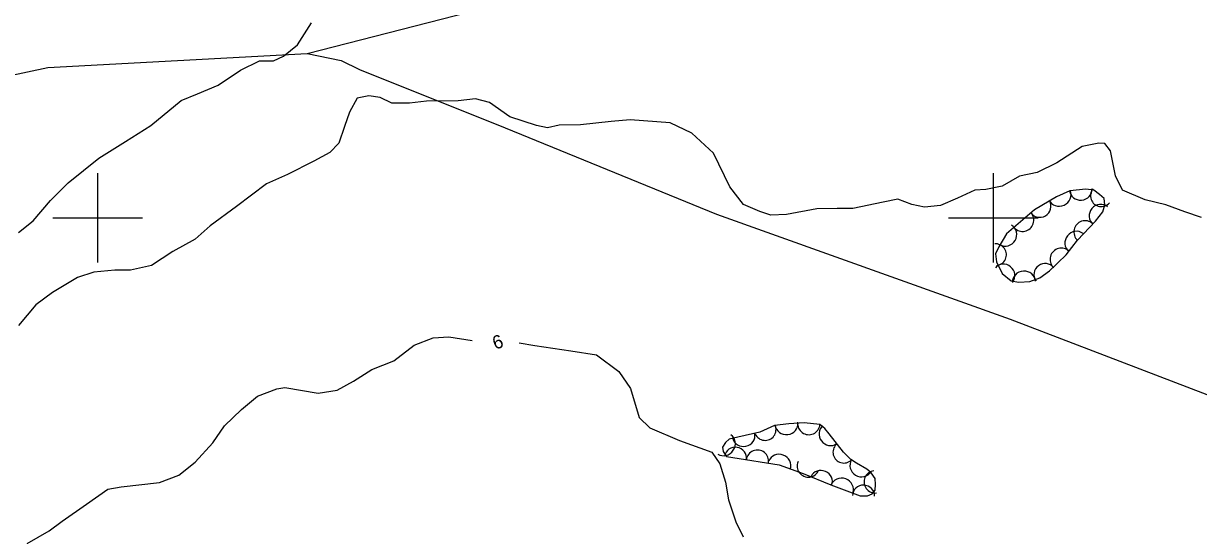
# Model space of a CAD drawing. Extents: x 643342 to 646936, y 5873857 to 5876103.
# Drawn here: x 645183.5 to 645445.8, y 5875329 to 5875443.4 of the extents above; entities that cross this region are included whole.
import ezdxf

# ---------------------------------------------------------------- set-up
doc = ezdxf.new("R2010")
doc.units = 0
for name, color, linetype in [('Niveau 1', 7, 'Continuous'), ('Niveau 2', 7, 'Continuous'), ('Niveau 22', 7, 'Continuous'), ('Niveau 44', 7, 'Continuous'), ('Niveau 61', 7, 'Continuous')]:
    doc.layers.add(name, color=color, linetype=linetype)

msp = doc.modelspace()

# ---------------------------------------------------------------- linework, layer by layer
at = {"layer": 'Niveau 1'}
msp.add_lwpolyline([(645182.37, 5875396.76), (645185.58, 5875399.33), (645189.49, 5875403.9), (645193.39, 5875407.82), (645196.82, 5875410.59), (645200.31, 5875413.3), (645206.2, 5875417.05), (645211.89, 5875420.6), (645218.67, 5875426.18), (645222.31, 5875427.74), (645226.91, 5875429.67), (645231.92, 5875432.99), (645236.15, 5875435.06), (645239.24, 5875435.05), (645241.47, 5875436.13), (645244.62, 5875438.63), (645247.79, 5875443.53)], dxfattribs=at)
at = {"layer": 'Niveau 2'}
for points in [[(645246.8, 5875436.74), (645309.81, 5875452.91), (645347.57, 5875463.16), (645370.52, 5875468.47), (645498.8, 5875495.97), (645554.04, 5875506.6), (645620.96, 5875521.54), (645671.93, 5875531.75), (645722.29, 5875544.6), (645729.55, 5875514.86), (645737.24, 5875468.76), (645738.05, 5875463.13)], [(645263.09, 5875426.89), (645260.56, 5875427.25), (645257.98, 5875426.72), (645256.22, 5875423.58), (645255.16, 5875420.44), (645253.87, 5875416.69), (645251.83, 5875414.63), (645248.28, 5875412.67), (645242.37, 5875409.68), (645237.72, 5875407.62), (645231, 5875402.51), (645225.14, 5875398.23), (645221.8, 5875395.23), (645216.79, 5875392.49), (645212.05, 5875389.37), (645207.31, 5875388.29), (645203.87, 5875388.28), (645199.12, 5875387.85), (645195.54, 5875386.7), (645189.95, 5875383.33), (645186.17, 5875380.58), (645182.37, 5875375.96)], [(645398.3, 5875406.32), (645395.88, 5875406.16), (645391.98, 5875404.41), (645388.23, 5875402.78), (645384.61, 5875402.39), (645381.83, 5875403.02), (645378.65, 5875404.14), (645375.4, 5875403.49), (645368.62, 5875402.06), (645365.14, 5875402.1), (645360.61, 5875402.04), (645353.81, 5875400.78), (645350.29, 5875400.58), (645347.89, 5875401.41), (645344.21, 5875402.95), (645341.18, 5875406.95), (645337.49, 5875414.45), (645332.67, 5875418.93), (645327.82, 5875421.19), (645318.93, 5875421.91), (645314.66, 5875421.52), (645307.8, 5875420.79), (645303.04, 5875420.71), (645300.42, 5875420.12), (645297.98, 5875420.66), (645292.06, 5875422.53), (645287.52, 5875425.75), (645284.37, 5875426.58), (645280.51, 5875426.11), (645273.47, 5875426.07), (645269.67, 5875425.61), (645265.71, 5875425.6), (645263.09, 5875426.89)], [(645446.51, 5875400.11), (645442.75, 5875401.34), (645438.49, 5875402.94), (645433.88, 5875403.99), (645428.87, 5875406.22), (645427.25, 5875409.41), (645426.18, 5875414.98), (645424.87, 5875416.61), (645423.59, 5875416.67), (645419.83, 5875415.92), (645414.19, 5875412.26), (645409.79, 5875410.16), (645405.87, 5875409.28), (645401.95, 5875407.06), (645398.3, 5875406.32)], [(645184.27, 5875327.23), (645189.17, 5875330.09), (645192.07, 5875332.23), (645197.52, 5875336.08), (645202.25, 5875339.39), (645205.24, 5875339.95), (645213.81, 5875340.91), (645218.16, 5875342.54), (645221.76, 5875345.39), (645225.7, 5875349.74), (645228.34, 5875353.56), (645232.1, 5875357.19), (645235.7, 5875360.16), (645240.05, 5875361.79), (645241.77, 5875362.12), (645249.23, 5875360.86), (645253.49, 5875361.54), (645257.11, 5875363.51), (645261.2, 5875366.11), (645266.15, 5875368.09), (645270.69, 5875371.55), (645274.92, 5875373.17), (645278.39, 5875373.42), (645283.66, 5875372.59)], [(645294.13, 5875372.12), (645297.63, 5875371.47), (645305.66, 5875370.27), (645311.39, 5875369.38), (645316.38, 5875365.67), (645318.99, 5875361.86), (645320.91, 5875355.41), (645323.32, 5875353.11), (645329.92, 5875350.26), (645337.15, 5875347.63), (645338.95, 5875345.04), (645340.19, 5875340.94), (645340.88, 5875337.01), (645342.54, 5875332.12), (645344.12, 5875328.75)]]:
    msp.add_lwpolyline(points, dxfattribs=at)
at = {"layer": 'Niveau 22'}
msp.add_lwpolyline([(644607.99, 5875276.54), (644615.34, 5875282.58), (644626.17, 5875289.28), (644635.97, 5875293.95), (644659.53, 5875302.81), (644722.84, 5875328.77), (644742.2, 5875336.13), (644757.56, 5875339.67), (644787.87, 5875347.1), (644846.76, 5875359.49), (644883.37, 5875366.24), (644949.1, 5875380.73), (645027.75, 5875398.1), (645075.65, 5875409.44), (645188.89, 5875433.56), (645246.8, 5875436.74), (645254.39, 5875435.12), (645258.48, 5875433.17), (645290.98, 5875420.13), (645338.2, 5875400.85), (645403.78, 5875377.34), (645494.14, 5875342.72), (645576.71, 5875308.93), (645614.3, 5875294.03)], dxfattribs=at)
at = {"layer": 'Niveau 44'}
for points in [[(645418.81, 5875395), (645422.8, 5875399.29), (645424.47, 5875401.31), (645424.91, 5875402.91), (645424.77, 5875404.36), (645423.71, 5875405.24), (645422.45, 5875406.19), (645420.67, 5875406.41), (645417.08, 5875406.07), (645414.08, 5875404.71), (645409.17, 5875401.8), (645402.93, 5875396.42), (645401.25, 5875393.52), (645400.52, 5875391.99), (645400.69, 5875390.15), (645402.01, 5875387.54), (645404.02, 5875385.97), (645405.71, 5875385.64), (645408.14, 5875385.78), (645410.41, 5875386.58), (645412.51, 5875388.15), (645416.28, 5875391.73), (645418.81, 5875395)], [(645361.29, 5875353.81), (645357.73, 5875354.25), (645354.32, 5875354.02), (645351.13, 5875353.62), (645347.84, 5875352.13), (645342.96, 5875350.98), (645341.04, 5875350.6), (645340.23, 5875349.84), (645339.54, 5875348.8), (645339.64, 5875347.83), (645340.42, 5875346.73), (645341.82, 5875346.47), (645352.16, 5875344.82), (645357.53, 5875342.89), (645363.74, 5875340.35), (645370.23, 5875337.94), (645371.9, 5875337.9), (645372.93, 5875338.39), (645373.64, 5875339.14), (645373.72, 5875340.42), (645373.59, 5875341.78), (645372.69, 5875343.06), (645371.73, 5875343.85), (645369.45, 5875345.2), (645368.19, 5875346.06), (645366.57, 5875347.66), (645363.35, 5875351.76), (645362.36, 5875352.93), (645361.29, 5875353.81)]]:
    msp.add_lwpolyline(points, dxfattribs=at)
for centre, major_axis, ratio, start_param, end_param in [((645414.81, 5875405.05), (2.37, 1.07), 0.925819, 3.141593, 6.283185), ((645419.53, 5875406.26), (2.49, 0.19), 0.919919, 3.141593, 6.283185), ((645424.12, 5875404.95), (-1.57, -1.86), 0.997449, 4.712389, 7.853982), ((645410.41, 5875402.54), (2.13, 1.26), 0.970147, 3.141593, 6.283185), ((645406.53, 5875399.46), (1.67, -1.86), 0.99999, 4.712389, 7.853982), ((645423.87, 5875400.53), (-1.64, -1.95), 0.952628, 3.141593, 6.283185), ((645402.76, 5875396.19), (1.3, 2.19), 0.952628, 3.141593, 6.283185), ((645420.48, 5875396.86), (-1.86, 1.67), 0.99999, 4.712389, 7.853982), ((645418.45, 5875394.49), (-1.58, -2), 0.952628, 3.141593, 6.283185), ((645400.5, 5875391.78), (2.42, 0.2), 0.997449, 4.712389, 7.853982), ((645415.17, 5875390.74), (-1.76, 1.78), 0.99999, 4.712389, 7.853982), ((645402.4, 5875387.29), (-1.94, 1.58), 0.919919, 3.141593, 6.283185), ((645406.84, 5875385.7), (-2.59, -0.14), 0.925819, 3.141593, 6.283185), ((645411.51, 5875387.39), (-1.98, -1.48), 0.970147, 3.141593, 6.283185), ((645349.06, 5875352.72), (0.98, -2.22), 0.997449, 4.712389, 7.853982), ((645353.82, 5875353.99), (2.53, 0.29), 0.952628, 3.141593, 6.283185), ((645358.8, 5875354.07), (-0.26, -2.49), 0.99999, 4.712389, 7.853982), ((645339.93, 5875349.4), (1.43, 2.17), 0.925819, 3.141593, 6.283185), ((645344.28, 5875351.25), (2.44, 0.52), 0.919919, 3.141593, 6.283185), ((645363.45, 5875351.55), (1.51, -1.99), 0.919919, 3.141593, 6.283185), ((645342.42, 5875346.37), (-2.44, 0.39), 0.970147, 3.141593, 6.283185), ((645366.62, 5875347.66), (-1.73, -1.71), 0.997449, 4.712389, 7.853982), ((645347.33, 5875345.63), (0.35, 2.48), 0.99999, 4.712389, 7.853982), ((645352.25, 5875344.75), (-2.39, 0.89), 0.952628, 3.141593, 6.283185), ((645370.5, 5875344.61), (2.18, -1.32), 0.952628, 3.141593, 6.283185), ((645358.69, 5875344.57), (-0.97, -2.3), 0.99999, 4.712389, 7.853982), ((645361.61, 5875341.26), (-2.29, 0.99), 0.919919, 3.141593, 6.283185), ((645373.62, 5875341.03), (-2.48, -0.28), 0.99999, 4.712389, 7.853982), ((645366.2, 5875339.43), (-2.44, 0.9), 0.925819, 3.141593, 6.283185), ((645371.01, 5875337.91), (-2.47, 0.05), 0.970147, 3.141593, 6.283185)]:
    msp.add_ellipse(centre, major_axis=major_axis, ratio=ratio, start_param=start_param, end_param=end_param, dxfattribs=at)
at = {"layer": 'Niveau 61'}
for points in [[(645200, 5875410), (645200, 5875400), (645200, 5875390)], [(645400, 5875410), (645400, 5875400), (645400, 5875390)], [(645190, 5875400), (645200, 5875400), (645210, 5875400)], [(645390, 5875400), (645400, 5875400), (645410, 5875400)]]:
    msp.add_lwpolyline(points, dxfattribs=at)

# ---------------------------------------------------------------- texts
at = {"layer": 'Niveau 2'}
msp.add_text('6', height=3, rotation=19.5753, dxfattribs=at).set_placement((645288.79, 5875370.51))

doc.saveas('drawing.dxf')
